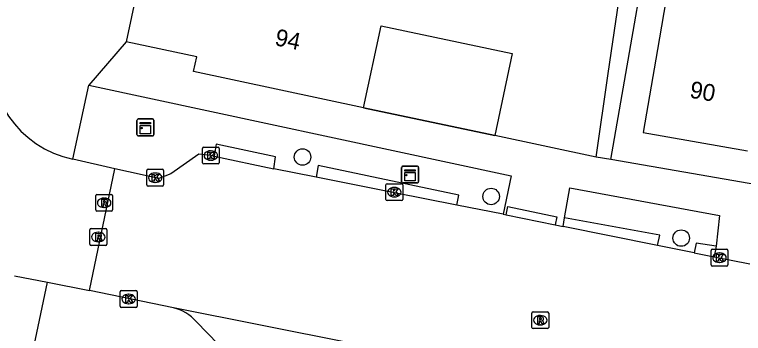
# Model space of a CAD drawing. Extents: x 163010 to 163853, y 382793 to 383982.
# Drawn here: x 163392.97 to 163436.22, y 383442.36 to 383461.27 of the extents above; entities that cross this region are included whole.
import ezdxf

# ---------------------------------------------------------------- set-up
doc = ezdxf.new("R2010")
doc.units = 0
for name, color, linetype in [('IMGEO_Boom', 7, 'Continuous'), ('IMGEO_Kast', 7, 'Continuous'), ('IMGEO_Kolk', 7, 'Continuous'), ('IMGEO_Muur', 7, 'Continuous'), ('IMGEO_Pand', 7, 'Continuous'), ('IMGEO_Pand_nummerreeks', 7, 'Continuous'), ('IMGEO_Parkeervlak_gesloten', 7, 'Continuous'), ('IMGEO_Rijbaan_lokaal_gesloten', 7, 'Continuous'), ('IMGEO_Rioolput', 7, 'Continuous'), ('IMGEO_Voetpad_open', 7, 'Continuous')]:
    doc.layers.add(name, color=color, linetype=linetype)

msp = doc.modelspace()

# ---------------------------------------------------------------- linework, layer by layer
at = {"layer": 'IMGEO_Boom'}
for centre in [(163410.053, 383452.823), (163421.244, 383450.483), (163432.524, 383448.016)]:
    msp.add_circle(centre, 0.489, dxfattribs=at)
at = {"layer": 'IMGEO_Kast'}
for p, q in [((163400.227, 383454.155), (163400.227, 383454.996)), ((163400.227, 383454.996), (163400.227, 383454.155)), ((163400.302, 383455.08), (163401.143, 383455.08)), ((163401.143, 383455.08), (163400.302, 383455.08)), ((163401.227, 383455.005), (163401.227, 383454.164)), ((163401.227, 383454.164), (163401.227, 383455.005)), ((163401.152, 383454.08), (163400.311, 383454.08)), ((163400.311, 383454.08), (163401.152, 383454.08)), ((163415.936, 383451.359), (163415.936, 383452.2)), ((163415.936, 383452.2), (163415.936, 383451.359)), ((163416.011, 383452.284), (163416.852, 383452.284)), ((163416.852, 383452.284), (163416.011, 383452.284)), ((163416.936, 383452.209), (163416.936, 383451.368)), ((163416.936, 383451.368), (163416.936, 383452.209)), ((163416.861, 383451.284), (163416.02, 383451.284)), ((163416.02, 383451.284), (163416.861, 383451.284))]:
    msp.add_line(p, q, dxfattribs=at)
for points in [[(163400.422, 383454.87), (163401.022, 383454.87), (163401.022, 383454.785), (163400.422, 383454.785), (163400.422, 383454.87)], [(163400.422, 383454.695), (163401.022, 383454.695), (163401.022, 383454.206), (163400.422, 383454.206), (163400.422, 383454.695)], [(163416.131, 383452.074), (163416.731, 383452.074), (163416.731, 383451.989), (163416.131, 383451.989), (163416.131, 383452.074)], [(163416.131, 383451.899), (163416.731, 383451.899), (163416.731, 383451.41), (163416.131, 383451.41), (163416.131, 383451.899)]]:
    msp.add_lwpolyline(points, dxfattribs=at)
for centre in [(163400.506, 383454.544), (163416.215, 383451.748)]:
    msp.add_circle(centre, 0.0377, dxfattribs=at)
for centre, start, end in [((163400.305, 383455.002), 92.4484, 184.2845), ((163400.305, 383455.002), 92.4484, 184.2845), ((163401.149, 383455.002), 2.4484, 94.2845), ((163401.149, 383455.002), 2.4484, 94.2845), ((163400.305, 383454.158), 182.4484, 274.2845), ((163400.305, 383454.158), 182.4484, 274.2845), ((163401.149, 383454.158), 272.4484, 4.2845), ((163401.149, 383454.158), 272.4484, 4.2845), ((163416.014, 383452.206), 92.4484, 184.2845), ((163416.014, 383452.206), 92.4484, 184.2845), ((163416.858, 383452.206), 2.4484, 94.2845), ((163416.858, 383452.206), 2.4484, 94.2845), ((163416.014, 383451.362), 182.4484, 274.2845), ((163416.014, 383451.362), 182.4484, 274.2845), ((163416.858, 383451.362), 272.4484, 4.2845), ((163416.858, 383451.362), 272.4484, 4.2845)]:
    msp.add_arc(centre, 0.0779, start, end, dxfattribs=at)
at = {"layer": 'IMGEO_Kolk'}
for p, q in [((163404.113, 383452.486), (163404.113, 383453.338)), ((163404.188, 383453.412), (163405.04, 383453.412)), ((163405.114, 383453.338), (163405.114, 383452.486)), ((163404.601, 383453.192), (163404.626, 383453.192)), ((163405.04, 383452.412), (163404.188, 383452.412)), ((163404.624, 383452.632), (163404.599, 383452.632)), ((163400.811, 383451.171), (163400.811, 383452.023)), ((163400.886, 383452.097), (163401.738, 383452.097)), ((163401.812, 383452.023), (163401.812, 383451.171)), ((163401.299, 383451.877), (163401.324, 383451.877)), ((163401.738, 383451.097), (163400.886, 383451.097)), ((163401.322, 383451.317), (163401.297, 383451.317)), ((163415, 383450.313), (163415, 383451.165)), ((163415.075, 383451.239), (163415.927, 383451.239)), ((163416.001, 383451.165), (163416.001, 383450.313)), ((163415.488, 383451.019), (163415.513, 383451.019)), ((163415.927, 383450.239), (163415.075, 383450.239)), ((163415.511, 383450.459), (163415.486, 383450.459)), ((163434.294, 383446.428), (163434.294, 383447.28)), ((163434.369, 383447.354), (163435.221, 383447.354)), ((163435.295, 383447.28), (163435.295, 383446.428)), ((163434.782, 383447.134), (163434.807, 383447.134)), ((163435.221, 383446.354), (163434.369, 383446.354)), ((163434.805, 383446.574), (163434.78, 383446.574)), ((163399.238, 383443.976), (163399.238, 383444.828)), ((163399.313, 383444.902), (163400.165, 383444.902)), ((163399.726, 383444.682), (163399.751, 383444.682)), ((163400.239, 383444.828), (163400.239, 383443.976)), ((163399.749, 383444.122), (163399.724, 383444.122)), ((163400.165, 383443.902), (163399.313, 383443.902))]:
    msp.add_line(p, q, dxfattribs=at)
for points in [[(163404.113, 383452.486), (163404.113, 383453.338)], [(163404.188, 383453.412), (163405.04, 383453.412)], [(163405.114, 383453.338), (163405.114, 383452.486)], [(163404.434, 383453.112), (163404.557, 383453.112), (163404.557, 383452.961), (163404.687, 383453.112), (163404.851, 383453.112), (163404.705, 383452.961), (163404.858, 383452.712), (163404.706, 383452.712), (163404.621, 383452.876), (163404.557, 383452.809), (163404.557, 383452.712), (163404.434, 383452.712), (163404.434, 383453.112)], [(163405.04, 383452.412), (163404.188, 383452.412)], [(163400.811, 383451.171), (163400.811, 383452.023)], [(163400.886, 383452.097), (163401.738, 383452.097)], [(163401.812, 383452.023), (163401.812, 383451.171)], [(163401.132, 383451.797), (163401.255, 383451.797), (163401.255, 383451.646), (163401.385, 383451.797), (163401.549, 383451.797), (163401.403, 383451.646), (163401.556, 383451.397), (163401.404, 383451.397), (163401.319, 383451.561), (163401.255, 383451.494), (163401.255, 383451.397), (163401.132, 383451.397), (163401.132, 383451.797)], [(163401.738, 383451.097), (163400.886, 383451.097)], [(163415, 383450.313), (163415, 383451.165)], [(163415.075, 383451.239), (163415.927, 383451.239)], [(163416.001, 383451.165), (163416.001, 383450.313)], [(163415.321, 383450.939), (163415.444, 383450.939), (163415.444, 383450.788), (163415.574, 383450.939), (163415.738, 383450.939), (163415.592, 383450.788), (163415.745, 383450.539), (163415.593, 383450.539), (163415.508, 383450.703), (163415.444, 383450.636), (163415.444, 383450.539), (163415.321, 383450.539), (163415.321, 383450.939)], [(163415.927, 383450.239), (163415.075, 383450.239)], [(163434.294, 383446.428), (163434.294, 383447.28)], [(163434.369, 383447.354), (163435.221, 383447.354)], [(163435.295, 383447.28), (163435.295, 383446.428)], [(163434.615, 383447.054), (163434.738, 383447.054), (163434.738, 383446.903), (163434.868, 383447.054), (163435.032, 383447.054), (163434.886, 383446.903), (163435.039, 383446.654), (163434.887, 383446.654), (163434.802, 383446.818), (163434.738, 383446.751), (163434.738, 383446.654), (163434.615, 383446.654), (163434.615, 383447.054)], [(163435.221, 383446.354), (163434.369, 383446.354)], [(163399.238, 383443.976), (163399.238, 383444.828)], [(163399.313, 383444.902), (163400.165, 383444.902)], [(163399.559, 383444.602), (163399.682, 383444.602), (163399.682, 383444.451), (163399.812, 383444.602), (163399.976, 383444.602), (163399.83, 383444.451), (163399.983, 383444.202), (163399.831, 383444.202), (163399.746, 383444.366), (163399.682, 383444.299), (163399.682, 383444.202), (163399.559, 383444.202), (163399.559, 383444.602)], [(163400.239, 383444.828), (163400.239, 383443.976)], [(163400.165, 383443.902), (163399.313, 383443.902)]]:
    msp.add_lwpolyline(points, dxfattribs=at)
for centre, start, end in [((163404.19, 383453.336), 91.552, 178.448), ((163404.19, 383453.336), 91.552, 178.448), ((163405.038, 383453.336), 1.552, 88.448), ((163405.038, 383453.336), 1.552, 88.448), ((163404.19, 383452.488), 181.552, 268.448), ((163404.19, 383452.488), 181.552, 268.448), ((163405.038, 383452.488), 271.552, 358.448), ((163405.038, 383452.488), 271.552, 358.448), ((163400.888, 383452.021), 91.552, 178.448), ((163400.888, 383452.021), 91.552, 178.448), ((163401.736, 383452.021), 1.552, 88.448), ((163401.736, 383452.021), 1.552, 88.448), ((163400.888, 383451.173), 181.552, 268.448), ((163400.888, 383451.173), 181.552, 268.448), ((163401.736, 383451.173), 271.552, 358.448), ((163401.736, 383451.173), 271.552, 358.448), ((163415.077, 383451.163), 91.552, 178.448), ((163415.077, 383451.163), 91.552, 178.448), ((163415.925, 383451.163), 1.552, 88.448), ((163415.925, 383451.163), 1.552, 88.448), ((163415.077, 383450.315), 181.552, 268.448), ((163415.077, 383450.315), 181.552, 268.448), ((163415.925, 383450.315), 271.552, 358.448), ((163415.925, 383450.315), 271.552, 358.448), ((163434.371, 383447.278), 91.552, 178.448), ((163434.371, 383447.278), 91.552, 178.448), ((163435.219, 383447.278), 1.552, 88.448), ((163435.219, 383447.278), 1.552, 88.448), ((163434.371, 383446.43), 181.552, 268.448), ((163434.371, 383446.43), 181.552, 268.448), ((163435.219, 383446.43), 271.552, 358.448), ((163435.219, 383446.43), 271.552, 358.448), ((163399.315, 383444.826), 91.552, 178.448), ((163399.315, 383444.826), 91.552, 178.448), ((163400.163, 383444.826), 1.552, 88.448), ((163400.163, 383444.826), 1.552, 88.448), ((163399.315, 383443.978), 181.552, 268.448), ((163399.315, 383443.978), 181.552, 268.448), ((163400.163, 383443.978), 271.552, 358.448), ((163400.163, 383443.978), 271.552, 358.448)]:
    msp.add_arc(centre, 0.0765, start, end, dxfattribs=at)
for centre, major_axis, ratio, start_param, end_param in [((163404.6, 383452.912), (-0.387, 0.002), 0.722429, 4.712389, 7.853982), ((163404.625, 383452.912), (-0.39, 0.002), 0.717154, 1.570796, 4.712389), ((163401.298, 383451.597), (-0.387, 0.002), 0.722429, 4.712389, 7.853982), ((163401.323, 383451.597), (-0.39, 0.002), 0.717154, 1.570796, 4.712389), ((163415.487, 383450.739), (-0.387, 0.002), 0.722429, 4.712389, 7.853982), ((163415.512, 383450.739), (-0.39, 0.002), 0.717154, 1.570796, 4.712389), ((163434.781, 383446.854), (-0.387, 0.002), 0.722429, 4.712389, 7.853982), ((163434.806, 383446.854), (-0.39, 0.002), 0.717154, 1.570796, 4.712389), ((163399.725, 383444.402), (-0.387, 0.002), 0.722429, 4.712389, 7.853982), ((163399.75, 383444.402), (-0.39, 0.002), 0.717154, 1.570796, 4.712389)]:
    msp.add_ellipse(centre, major_axis=major_axis, ratio=ratio, start_param=start_param, end_param=end_param, dxfattribs=at)
at = {"layer": 'IMGEO_Muur'}
msp.add_lwpolyline([(163413.676, 383455.743), (163421.457, 383454.107)], dxfattribs=at)
at = {"layer": 'IMGEO_Pand'}
for points in [[(163404.304, 383473.612), (163401.161, 383467.091), (163399.578, 383459.666)], [(163437.953, 383461.714), (163437.6, 383461.776), (163438.076, 383464.503), (163432.183, 383465.53), (163431.726, 383462.8), (163431.123, 383459.2), (163430.262, 383454.274), (163436.462, 383453.19)], [(163427.483, 383452.823), (163428.197, 383457.772), (163428.917, 383462.769)], [(163413.676, 383455.743), (163414.714, 383460.614), (163422.491, 383458.958), (163421.457, 383454.107)], [(163413.676, 383455.743), (163403.592, 383457.892), (163403.779, 383458.771), (163399.578, 383459.666)], [(163427.483, 383452.823), (163421.457, 383454.107)]]:
    msp.add_lwpolyline(points, dxfattribs=at)
at = {"layer": 'IMGEO_Parkeervlak_gesloten'}
msp.add_lwpolyline([(163406.208, 383441.337), (163405.738, 383441.444), (163405.071, 383441.704), (163403.739, 383443.064)], dxfattribs=at)
msp.add_arc((163401.869, 383441.473), 2.455, 40.3962, 77.7263, dxfattribs=at)
at = {"layer": 'IMGEO_Rijbaan_lokaal_gesloten'}
for points in [[(163404.817, 383452.868), (163404.614, 383452.912), (163403.898, 383452.994), (163402.236, 383451.819), (163401.528, 383451.546), (163398.906, 383452.115)], [(163404.817, 383452.868), (163408.35, 383452.121)], [(163398.906, 383452.115), (163396.426, 383452.704)], [(163397.414, 383444.913), (163398.906, 383452.115)], [(163410.863, 383451.623), (163408.35, 383452.121)], [(163419.215, 383449.969), (163415.506, 383450.701), (163410.863, 383451.623)], [(163421.958, 383449.428), (163419.215, 383449.969)], [(163421.958, 383449.428), (163422.135, 383449.393)], [(163422.135, 383449.393), (163425.05, 383448.796)], [(163425.05, 383448.796), (163425.519, 383448.702)], [(163431.116, 383447.585), (163425.519, 383448.702)], [(163433.299, 383447.149), (163431.116, 383447.585)], [(163433.299, 383447.149), (163434.488, 383446.911)], [(163434.488, 383446.911), (163436.6, 383446.49)], [(163392.966, 383445.785), (163394.919, 383445.402)], [(163394.919, 383445.402), (163397.414, 383444.913)], [(163402.391, 383443.872), (163397.414, 383444.913)], [(163489.302, 383429.542), (163435.77, 383437.524), (163418.179, 383440.744), (163402.391, 383443.872)]]:
    msp.add_lwpolyline(points, dxfattribs=at)
msp.add_arc((163397.609, 383458.596), 6.01, 168.9198, 258.6515, dxfattribs=at)
at = {"layer": 'IMGEO_Rioolput'}
for p, q in [((163397.857, 383450.611), (163398.709, 383450.611)), ((163397.782, 383449.685), (163397.782, 383450.537)), ((163398.27, 383450.391), (163398.295, 383450.391)), ((163398.783, 383450.537), (163398.783, 383449.685)), ((163398.293, 383449.831), (163398.268, 383449.831)), ((163398.709, 383449.611), (163397.857, 383449.611)), ((163397.437, 383447.653), (163397.437, 383448.505)), ((163397.512, 383448.579), (163398.364, 383448.579)), ((163398.438, 383448.505), (163398.438, 383447.653)), ((163397.925, 383448.359), (163397.95, 383448.359)), ((163397.948, 383447.799), (163397.923, 383447.799)), ((163398.364, 383447.579), (163397.512, 383447.579)), ((163423.66, 383442.718), (163423.66, 383443.57)), ((163423.735, 383443.644), (163424.587, 383443.644)), ((163424.148, 383443.424), (163424.173, 383443.424)), ((163424.661, 383443.57), (163424.661, 383442.718)), ((163424.171, 383442.864), (163424.146, 383442.864)), ((163424.587, 383442.644), (163423.735, 383442.644))]:
    msp.add_line(p, q, dxfattribs=at)
for points in [[(163397.857, 383450.611), (163398.709, 383450.611)], [(163397.782, 383449.685), (163397.782, 383450.537)], [(163398.371, 383450.309), (163398.119, 383450.311), (163398.119, 383449.911)], [(163398.297, 383450.23), (163398.243, 383450.23), (163398.243, 383450.149)], [(163398.783, 383450.537), (163398.783, 383449.685)], [(163398.119, 383449.911), (163398.243, 383449.911), (163398.243, 383450.073), (163398.254, 383450.073)], [(163398.243, 383450.149), (163398.295, 383450.149)], [(163398.301, 383450.044), (163398.372, 383449.911), (163398.512, 383449.911), (163398.447, 383450.037)], [(163398.709, 383449.611), (163397.857, 383449.611)], [(163397.437, 383447.653), (163397.437, 383448.505)], [(163397.512, 383448.579), (163398.364, 383448.579)], [(163398.438, 383448.505), (163398.438, 383447.653)], [(163398.026, 383448.277), (163397.774, 383448.279), (163397.774, 383447.879)], [(163397.774, 383447.879), (163397.898, 383447.879), (163397.898, 383448.041), (163397.909, 383448.041)], [(163397.952, 383448.198), (163397.898, 383448.198), (163397.898, 383448.117)], [(163397.898, 383448.117), (163397.95, 383448.117)], [(163397.956, 383448.012), (163398.027, 383447.879), (163398.167, 383447.879), (163398.102, 383448.005)], [(163398.364, 383447.579), (163397.512, 383447.579)], [(163423.66, 383442.718), (163423.66, 383443.57)], [(163423.735, 383443.644), (163424.587, 383443.644)], [(163424.249, 383443.342), (163423.997, 383443.344), (163423.997, 383442.944)], [(163424.175, 383443.263), (163424.121, 383443.263), (163424.121, 383443.182)], [(163424.661, 383443.57), (163424.661, 383442.718)], [(163423.997, 383442.944), (163424.121, 383442.944), (163424.121, 383443.106), (163424.132, 383443.106)], [(163424.121, 383443.182), (163424.173, 383443.182)], [(163424.179, 383443.077), (163424.25, 383442.944), (163424.39, 383442.944), (163424.325, 383443.07)], [(163424.587, 383442.644), (163423.735, 383442.644)]]:
    msp.add_lwpolyline(points, dxfattribs=at)
for centre, radius, start, end in [((163397.859, 383450.535), 0.0765, 91.552, 178.448), ((163397.859, 383450.535), 0.0765, 91.552, 178.448), ((163398.707, 383450.535), 0.0765, 1.552, 88.448), ((163398.707, 383450.535), 0.0765, 1.552, 88.448), ((163398.303, 383450.134), 0.0964, 77.0061, 93.1865), ((163398.317, 383450.191), 0.0378, 276.6634, 79.6772), ((163398.37, 383450.199), 0.109, 350.3612, 89.416), ((163398.368, 383450.199), 0.112, 277.5842, 350.9817), ((163398.253, 383450.02), 0.0533, 26.0293, 88.6989), ((163398.279, 383450.338), 0.19, 274.7715, 282.9687), ((163398.352, 383449.984), 0.108, 29.5134, 73.7905), ((163397.859, 383449.687), 0.0765, 181.552, 268.448), ((163397.859, 383449.687), 0.0765, 181.552, 268.448), ((163398.707, 383449.687), 0.0765, 271.552, 358.448), ((163398.707, 383449.687), 0.0765, 271.552, 358.448), ((163397.514, 383448.503), 0.0765, 91.552, 178.448), ((163397.514, 383448.503), 0.0765, 91.552, 178.448), ((163398.362, 383448.503), 0.0765, 1.552, 88.448), ((163398.362, 383448.503), 0.0765, 1.552, 88.448), ((163397.908, 383447.988), 0.0533, 26.0293, 88.6989), ((163397.934, 383448.306), 0.19, 274.7715, 282.9687), ((163397.958, 383448.102), 0.0964, 77.0061, 93.1865), ((163397.972, 383448.159), 0.0378, 276.6634, 79.6772), ((163398.025, 383448.167), 0.109, 350.3612, 89.416), ((163398.023, 383448.167), 0.112, 277.5842, 350.9817), ((163398.007, 383447.952), 0.108, 29.5134, 73.7905), ((163397.514, 383447.655), 0.0765, 181.552, 268.448), ((163397.514, 383447.655), 0.0765, 181.552, 268.448), ((163398.362, 383447.655), 0.0765, 271.552, 358.448), ((163398.362, 383447.655), 0.0765, 271.552, 358.448), ((163423.737, 383443.568), 0.0765, 91.552, 178.448), ((163423.737, 383443.568), 0.0765, 91.552, 178.448), ((163424.181, 383443.167), 0.0964, 77.0061, 93.1865), ((163424.195, 383443.224), 0.0378, 276.6634, 79.6772), ((163424.248, 383443.232), 0.109, 350.3612, 89.416), ((163424.585, 383443.568), 0.0765, 1.552, 88.448), ((163424.585, 383443.568), 0.0765, 1.552, 88.448), ((163424.131, 383443.053), 0.0533, 26.0293, 88.6989), ((163424.157, 383443.371), 0.19, 274.7715, 282.9687), ((163424.246, 383443.232), 0.112, 277.5842, 350.9817), ((163424.23, 383443.017), 0.108, 29.5134, 73.7905), ((163423.737, 383442.72), 0.0765, 181.552, 268.448), ((163423.737, 383442.72), 0.0765, 181.552, 268.448), ((163424.585, 383442.72), 0.0765, 271.552, 358.448), ((163424.585, 383442.72), 0.0765, 271.552, 358.448)]:
    msp.add_arc(centre, radius, start, end, dxfattribs=at)
for centre, major_axis, ratio, start_param, end_param in [((163398.269, 383450.111), (-0.387, 0.002), 0.722429, 4.712389, 7.853982), ((163398.294, 383450.111), (-0.39, 0.002), 0.717154, 1.570796, 4.712389), ((163397.924, 383448.079), (-0.387, 0.002), 0.722429, 4.712389, 7.853982), ((163397.949, 383448.079), (-0.39, 0.002), 0.717154, 1.570796, 4.712389), ((163424.147, 383443.144), (-0.387, 0.002), 0.722429, 4.712389, 7.853982), ((163424.172, 383443.144), (-0.39, 0.002), 0.717154, 1.570796, 4.712389)]:
    msp.add_ellipse(centre, major_axis=major_axis, ratio=ratio, start_param=start_param, end_param=end_param, dxfattribs=at)
at = {"layer": 'IMGEO_Voetpad_open'}
for points in [[(163428.344, 383452.674), (163431.455, 383470.492), (163446.555, 383501.65)], [(163399.578, 383459.666), (163397.375, 383457.091)], [(163396.426, 383452.704), (163397.375, 383457.091)], [(163397.375, 383457.091), (163422.432, 383451.713), (163421.958, 383449.428)], [(163421.457, 383454.107), (163413.676, 383455.743)], [(163408.35, 383452.121), (163408.447, 383452.84), (163404.932, 383453.588), (163404.817, 383452.868)], [(163428.344, 383452.674), (163427.483, 383452.823)], [(163491.869, 383443.04), (163443.743, 383450.007), (163428.344, 383452.674)], [(163419.215, 383449.969), (163419.322, 383450.565), (163410.991, 383452.329), (163410.863, 383451.623)], [(163425.6, 383449.212), (163425.913, 383451.001), (163434.805, 383449.354), (163434.59, 383447.541)], [(163422.135, 383449.393), (163422.236, 383449.888), (163425.149, 383449.282), (163425.05, 383448.796)], [(163425.519, 383448.702), (163425.6, 383449.212)], [(163431.116, 383447.585), (163431.246, 383448.198), (163425.6, 383449.212)], [(163434.59, 383447.541), (163433.403, 383447.716), (163433.299, 383447.149)], [(163434.59, 383447.541), (163434.488, 383446.911)], [(163407.698, 383440.256), (163407.279, 383438.473), (163394.055, 383441.268), (163394.919, 383445.402)]]:
    msp.add_lwpolyline(points, dxfattribs=at)

# ---------------------------------------------------------------- texts
at = {"layer": 'IMGEO_Pand_nummerreeks'}
for s, rotation, p in [('94', 347.9392, (163408.36, 383459.468)), ('90', 350.0821, (163432.986, 383456.356))]:
    msp.add_text(s, height=1, rotation=rotation, dxfattribs=at).set_placement(p)

doc.saveas('drawing.dxf')
